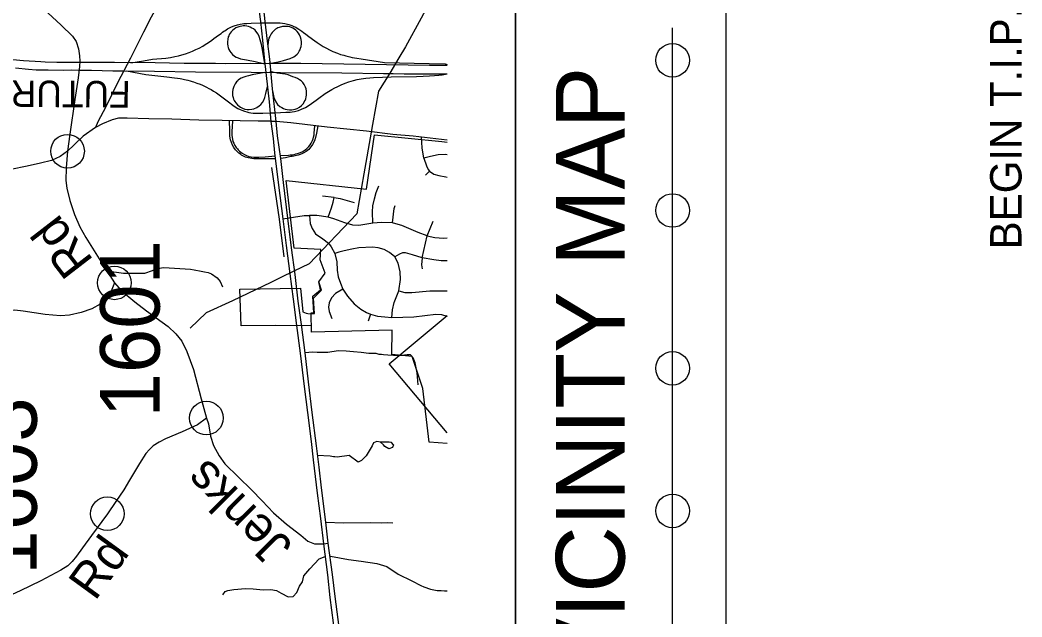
# Model space of a CAD drawing. Extents: x 2026893 to 2039781, y 729195 to 739590.
# Drawn here: x 2027941 to 2028835, y 735115 to 735647 of the extents above; entities that cross this region are included whole.
import ezdxf

# ---------------------------------------------------------------- set-up
doc = ezdxf.new("R2010")
doc.units = 0
doc.layers.add('Old_Level_1', color=7, linetype='Continuous')
doc.layers.add('Old_Level_62', color=7, linetype='Continuous')

msp = doc.modelspace()

# ---------------------------------------------------------------- linework, layer by layer
at = {"layer": 'Old_Level_62'}
for p, q in [((2028523.33, 735033.09), (2028523.33, 735639.94)), ((2027994.64, 735609.1), (2027985.25, 735609.2)), ((2028163.69, 735608.16), (2028159.75, 735608.02)), ((2027986.93, 735602.56), (2027993.99, 735602.17)), ((2027993.99, 735602.17), (2028005.07, 735602.27)), ((2028033.94, 735601.72), (2028061.39, 735601.53)), ((2028159.82, 735600.37), (2028164.29, 735600.62)), ((2028164.41, 735564.14), (2028168.85, 735564.38)), ((2028169.73, 735556.58), (2028165.13, 735556.67)), ((2028306.52, 735512.27), (2028302.91, 735508.83)), ((2028221.56, 735488.9), (2028211.25, 735490)), ((2028304.39, 735454.65), (2028309.91, 735467.73)), ((2028300.15, 735435.14), (2028304.39, 735454.65)), ((2028018.74, 735423.41), (2028025.55, 735412.72)), ((2028185.6, 735423.07), (2028174.06, 735417.51)), ((2028253.8, 735384.7), (2028251.78, 735378.44)), ((2028212.14, 735180.15), (2028216.13, 735180.6))]:
    msp.add_line(p, q, dxfattribs=at)
for points in [[(2027195.27, 734565.89), (2027195.27, 736091.37), (2028383.21, 736091.37), (2028383.21, 734565.89)], [(2028383.21, 734565.89), (2028383.21, 736091.37), (2028570.79, 736091.37), (2028570.79, 734565.89)]]:
    msp.add_lwpolyline(points, close=True, dxfattribs=at)
for points in [[(2027869.52, 735781.98), (2027871.69, 735772.47), (2027872.9, 735768.1), (2027876.18, 735762.11), (2027884.25, 735751.35), (2027895.8, 735736.41), (2027909.27, 735717.87), (2027923.14, 735699.41), (2027933.81, 735686.04), (2027947.48, 735671.05), (2027962.36, 735656.86), (2027977.92, 735642.45), (2027988.16, 735632.6), (2027991.44, 735627.77), (2027993.37, 735621.31), (2027994.44, 735615.03), (2027994.73, 735610.2), (2027994.34, 735605.47), (2027993.23, 735595.53), (2027990.33, 735576.05), (2027985.79, 735545.25), (2027983.71, 735530.05)], [(2028142.72, 735779.53), (2028136.67, 735775.93), (2028131.55, 735772.65), (2028126.43, 735768.5), (2028122.67, 735763.96), (2028114.65, 735752.81), (2028104.7, 735736.23), (2028093.68, 735716.15), (2028077.89, 735686.36), (2028069.34, 735669.59), (2028058.18, 735649.6), (2028051.51, 735636.09), (2028040.01, 735613.13), (2028028.32, 735591.15), (2028017.74, 735569.71), (2028010.69, 735556.29), (2028008.66, 735551.2)], [(2028142.72, 735779.53), (2028144.58, 735762.97), (2028146.18, 735746.9), (2028150.25, 735700.77), (2028152.64, 735669.87), (2028155.92, 735645.7), (2028157.69, 735628.92), (2028159.46, 735610.68), (2028163.44, 735574.12), (2028165.13, 735556.67)], [(2028169.73, 735556.58), (2028166.45, 735585.63), (2028164.15, 735612.19), (2028162.12, 735628.21), (2028159.99, 735645.7), (2028157.95, 735665.71), (2028155.21, 735699.36), (2028153, 735721.58), (2028146.54, 735780.87)], [(2028312.93, 735674.21), (2028299.19, 735648.77), (2028285.22, 735623.05), (2028279.33, 735613.22)], [(2028040.07, 735608.85), (2028051.44, 735610.63), (2028059.43, 735612.03), (2028071.52, 735613.07), (2028075.49, 735613.71), (2028079.46, 735614.41), (2028082.71, 735615.1), (2028085.79, 735615.9), (2028089.07, 735616.94), (2028092.09, 735617.98), (2028095.32, 735619.33), (2028098.23, 735620.62), (2028101.01, 735622.01), (2028104.3, 735623.8), (2028106.51, 735625.08), (2028109.58, 735627.07), (2028112.43, 735629.09), (2028114.34, 735630.45), (2028118.24, 735633.39), (2028120.6, 735635.12), (2028122.08, 735636.23), (2028123.21, 735637.03), (2028123.92, 735637.51), (2028125.15, 735638.3), (2028126.42, 735639.05), (2028127.47, 735639.65), (2028128.68, 735640.24), (2028130.1, 735640.93), (2028132.45, 735641.89), (2028135.32, 735642.76), (2028137.66, 735643.32), (2028139.62, 735643.61), (2028141.06, 735643.8), (2028143.75, 735643.98), (2028147.44, 735644.12), (2028156.03, 735644.62)], [(2028159.75, 735608.02), (2028157.68, 735620.82), (2028156.77, 735625.25), (2028155.66, 735629.28), (2028154.66, 735632.2), (2028153.65, 735634.52), (2028152.64, 735635.93), (2028150.93, 735637.94), (2028149.5, 735639.08), (2028148.11, 735639.88), (2028146.53, 735640.71), (2028145.02, 735641.19), (2028143.71, 735641.5), (2028141.8, 735641.74), (2028140.33, 735641.78), (2028139.06, 735641.66), (2028137.51, 735641.35), (2028135.61, 735640.71), (2028133.9, 735639.96), (2028132.43, 735638.96), (2028131.12, 735637.87), (2028129.69, 735636.38), (2028128.71, 735635.18), (2028128, 735634.03), (2028127.51, 735632.92), (2028127.11, 735632), (2028126.56, 735629.99), (2028126.36, 735627.71), (2028126.36, 735625.74), (2028126.67, 735623.84), (2028126.99, 735622.53), (2028127.69, 735620.82), (2028128.6, 735619.21), (2028129.27, 735618.2), (2028130.84, 735616.31), (2028132.77, 735614.77), (2028134.17, 735613.96), (2028135.88, 735613.19), (2028137.94, 735612.45), (2028143.22, 735611.38), (2028151.13, 735610.08), (2028159.75, 735608.02)], [(2028156.03, 735644.62), (2028165.47, 735644.6), (2028171.31, 735644.6), (2028173.35, 735644.45), (2028175.5, 735644.21), (2028177.46, 735643.95), (2028181.05, 735643.06), (2028183.78, 735642.1), (2028185.51, 735641.37), (2028187.2, 735640.6), (2028188.63, 735639.75), (2028190.16, 735638.79), (2028192.63, 735637.19), (2028194.31, 735635.97), (2028196.34, 735634.42), (2028198.95, 735632.42), (2028200.87, 735630.96), (2028202.2, 735629.92), (2028206.23, 735627.03), (2028208.97, 735625.15), (2028211.62, 735623.47), (2028214.01, 735622.15), (2028217.82, 735620.21), (2028220.47, 735619.04), (2028224.38, 735617.41), (2028227.28, 735616.43), (2028230.12, 735615.55), (2028231.96, 735614.99), (2028235.49, 735614.14), (2028237.48, 735613.71), (2028241.88, 735612.93), (2028245.61, 735612.47), (2028266.41, 735609.1), (2028306.13, 735608.37), (2028320.38, 735607.83), (2028322.2, 735607.51)], [(2028163.69, 735608.16), (2028171.53, 735609.79), (2028176.39, 735610.93), (2028182.29, 735612.74), (2028185.62, 735614.27), (2028186.84, 735615.13), (2028188.4, 735616.45), (2028189.42, 735617.59), (2028190.44, 735619.15), (2028191.1, 735620.41), (2028191.64, 735621.91), (2028192.18, 735623.53), (2028192.48, 735625.7), (2028192.54, 735627.5), (2028192.18, 735629.72), (2028191.64, 735631.64), (2028190.74, 735633.8), (2028189.72, 735635.42), (2028188.48, 735636.93), (2028187.28, 735638.03), (2028186.25, 735638.87), (2028184.61, 735639.88), (2028183.5, 735640.35), (2028182.69, 735640.64), (2028181.96, 735640.83), (2028180.56, 735641.14), (2028179.54, 735641.29), (2028178.47, 735641.37), (2028176.69, 735641.33), (2028175.54, 735641.25), (2028174.55, 735641.08), (2028173.42, 735640.75), (2028172.43, 735640.4), (2028171.31, 735639.93), (2028170.32, 735639.44), (2028169.22, 735638.75), (2028168.34, 735638.01), (2028167.33, 735637.1), (2028166.11, 735635.81), (2028165.37, 735634.74), (2028164.63, 735633.44), (2028164.11, 735632.33), (2028163.37, 735630.85), (2028163, 735629.29), (2028162.6, 735627), (2028162.41, 735624.9)], [(2028279.33, 735613.22), (2028271.25, 735599.74), (2028261.09, 735583.52), (2028255.77, 735553.87), (2028254.57, 735547.13)], [(2027985.25, 735609.2), (2027978.34, 735609.29), (2027974.08, 735609.19), (2027963.64, 735609.55), (2027959.87, 735609.68), (2027944.5, 735610.65), (2027935.04, 735611.58)], [(2027937.32, 735604.3), (2027949.02, 735603.23), (2027955.86, 735602.75), (2027961.27, 735602.56), (2027966.49, 735602.65), (2027979.81, 735602.36), (2027986.93, 735602.56)], [(2028037.81, 735608.99), (2028025.68, 735609.04), (2028002.19, 735609.29), (2027994.66, 735609.2)], [(2028159.75, 735608.02), (2028146.58, 735608.37), (2028124.75, 735608.03), (2028115.79, 735608.14), (2028087.74, 735608.27), (2028048.74, 735609.04), (2028037.81, 735608.99)], [(2028322.2, 735606.39), (2028306.45, 735606.57), (2028191.72, 735608.22), (2028182.43, 735608.13), (2028168.44, 735608.28), (2028163.69, 735608.16)], [(2028005.07, 735602.27), (2028024.21, 735601.59), (2028033.94, 735601.72)], [(2028036.42, 735601.58), (2028053.64, 735598.57), (2028072.21, 735596.26), (2028079.21, 735595.62), (2028081.87, 735595.2), (2028084.18, 735594.78), (2028085.79, 735594.57), (2028088.1, 735594.08), (2028091.04, 735593.31), (2028093, 735592.75), (2028094.89, 735592.26), (2028096.15, 735591.91), (2028099.13, 735590.79), (2028102, 735589.74), (2028104.14, 735588.82), (2028107.56, 735587.21), (2028109.81, 735585.98), (2028111.77, 735584.95), (2028113.87, 735583.68), (2028116.51, 735582.07), (2028118.86, 735580.45), (2028121.35, 735578.64), (2028124.88, 735575.9), (2028127.32, 735573.99), (2028131.13, 735571.17), (2028133.14, 735569.75), (2028135.71, 735568.27), (2028137.66, 735567.22), (2028139.27, 735566.54), (2028141.42, 735565.7), (2028143.7, 735565.04), (2028145.32, 735564.56), (2028147.18, 735564.26), (2028149.22, 735563.96), (2028151.43, 735563.84), (2028153.11, 735563.84), (2028157.79, 735563.9), (2028164.41, 735564.14)], [(2028061.39, 735601.53), (2028097.95, 735600.92), (2028147.46, 735600.58), (2028159.82, 735600.37)], [(2028159.82, 735600.37), (2028148.29, 735598.05), (2028145.07, 735597.38), (2028142.74, 735596.65), (2028140.85, 735596.18), (2028138.65, 735595.15), (2028137.2, 735594.25), (2028135.98, 735593.38), (2028135.51, 735592.95), (2028134.49, 735591.81), (2028133.15, 735590.07), (2028131.9, 735587.63), (2028131.08, 735585.11), (2028130.82, 735583.03), (2028130.79, 735581.11), (2028130.97, 735579.67), (2028131.34, 735578.08), (2028131.86, 735576.53), (2028132.38, 735575.38), (2028132.93, 735574.27), (2028133.74, 735573.19), (2028135.35, 735571.36), (2028136.78, 735570.21), (2028138.1, 735569.23), (2028139.82, 735568.37), (2028141.83, 735567.68), (2028143.95, 735567.28), (2028145.73, 735567.17), (2028148.03, 735567.45), (2028150.03, 735567.97), (2028152.67, 735569.12), (2028154.62, 735570.5), (2028156.17, 735571.76), (2028157.61, 735573.48), (2028158.75, 735575.43), (2028159.79, 735578.02), (2028160.63, 735581.37), (2028162.03, 735587.65)], [(2028163.96, 735600.6), (2028173.72, 735600.29), (2028228.35, 735599.85), (2028265.41, 735599.44), (2028274.03, 735599.3), (2028283.98, 735599.04), (2028322.2, 735599.11)], [(2028166.55, 735583.96), (2028167.84, 735578.02), (2028169.44, 735574.16), (2028171.05, 735571.83), (2028173.13, 735570.07), (2028174.9, 735568.89), (2028176.2, 735568.21), (2028177.9, 735567.53), (2028179.54, 735567.14), (2028181.69, 735566.91), (2028183.9, 735566.97), (2028186.73, 735567.59), (2028188.54, 735568.27), (2028190.53, 735569.35), (2028192.45, 735570.93), (2028194.04, 735572.69), (2028194.89, 735574.05), (2028195.57, 735575.3), (2028196.13, 735576.71), (2028196.59, 735578.47), (2028196.87, 735580.06), (2028196.98, 735581.59), (2028196.87, 735583.51), (2028196.42, 735585.67), (2028195.91, 735587.2), (2028194.66, 735589.51), (2028193.44, 735591.24), (2028191.98, 735592.7), (2028190.49, 735593.84), (2028188.76, 735594.84), (2028186.75, 735595.75), (2028184.63, 735596.38), (2028180.53, 735598.13), (2028177.74, 735598.66), (2028170.76, 735599.53), (2028165.7, 735600.93)], [(2028168.85, 735564.38), (2028178.37, 735564.8), (2028182.14, 735564.92), (2028184.09, 735565.09), (2028186.05, 735565.46), (2028189.65, 735566.32), (2028192.47, 735567.42), (2028196.08, 735569.13), (2028199.38, 735571.15), (2028205.43, 735575.56), (2028207.94, 735577.45), (2028213.55, 735581.5), (2028216.5, 735583.42), (2028219.42, 735585.17), (2028222.1, 735586.65), (2028224.12, 735587.59), (2028227.9, 735589.31), (2028231.2, 735590.6), (2028234.71, 735591.83), (2028238.88, 735593.02), (2028242.07, 735593.85), (2028245.71, 735594.57), (2028249.67, 735595.19), (2028253.23, 735595.55), (2028256.48, 735595.86), (2028264.75, 735596.06), (2028272.43, 735596.47), (2028294.87, 735596.73), (2028300.79, 735596.99), (2028306.62, 735597.25), (2028311.05, 735597.55), (2028314.86, 735597.81), (2028317.9, 735598.07), (2028322.2, 735599.01)], [(2028165.13, 735556.67), (2028164.79, 735556.8), (2028153.87, 735556.9), (2028121.7, 735557.43), (2028100.73, 735557.62), (2028076.68, 735558.54), (2028056.1, 735559.02), (2028036.78, 735559.65), (2028029.24, 735559.55), (2028023.64, 735558.01), (2028014.85, 735554.34), (2028008.66, 735551.2)], [(2028008.66, 735551.2), (2027997.75, 735543.48), (2027989.63, 735535.85), (2027983.71, 735530.05)], [(2028169.03, 735523.39), (2028163.71, 735523.42), (2028159.74, 735523.35), (2028154.27, 735523.26), (2028151.81, 735523.3), (2028149.75, 735523.34), (2028148.02, 735523.49), (2028146.66, 735523.74), (2028144.79, 735524.13), (2028142.5, 735524.9), (2028140.57, 735525.71), (2028138.9, 735526.67), (2028138.03, 735527.29), (2028136.49, 735528.42), (2028134.98, 735529.75), (2028133.44, 735531.41), (2028132, 735533.41), (2028130.8, 735535.57), (2028129.89, 735537.72), (2028129.15, 735540.12), (2028128.6, 735543.51), (2028128.41, 735545.97), (2028128.47, 735548.43), (2028128.1, 735557.23)], [(2028131, 735557.23), (2028130.26, 735547.37), (2028130.32, 735544.11), (2028130.75, 735540.91), (2028131.24, 735538.81), (2028131.98, 735537.28), (2028132.97, 735535.3), (2028134.2, 735533.46), (2028135.24, 735532.16), (2028135.98, 735531.24), (2028137.14, 735530.12), (2028139.46, 735528.28), (2028141.64, 735527), (2028143.43, 735526.19), (2028145.42, 735525.48), (2028147.36, 735525.1), (2028149.82, 735524.82), (2028151.71, 735524.68), (2028154.26, 735524.73), (2028159.97, 735524.92), (2028168.81, 735525.86)], [(2028165.13, 735556.67), (2028167.07, 735541.4), (2028168.4, 735528.52), (2028171.85, 735499.7), (2028175.84, 735469.73), (2028178.85, 735446), (2028181.86, 735420.81), (2028184.87, 735398.19), (2028187.88, 735374.77), (2028191.25, 735350.06), (2028194.79, 735320.36), (2028197.8, 735297.12), (2028200.9, 735271.26), (2028202.84, 735254.84), (2028206.3, 735225.09), (2028209.22, 735202.78), (2028212.14, 735180.15)], [(2028216.13, 735180.6), (2028214.01, 735199.28), (2028210.28, 735230.09), (2028208.07, 735248.55), (2028205.85, 735267.28), (2028202.05, 735297.2), (2028198.77, 735324.43), (2028195.67, 735350.42), (2028192.31, 735375.47), (2028189.56, 735396.33), (2028186.64, 735420.19), (2028183.45, 735444.05), (2028180.35, 735470.52), (2028176.37, 735502.18), (2028173.98, 735523.65), (2028171.06, 735543.7), (2028169.73, 735556.58)], [(2028322.2, 735539.88), (2028291.85, 735543.38), (2028273.84, 735545.1), (2028250.28, 735547.83), (2028215.31, 735551.47), (2028182.74, 735555.25), (2028169.73, 735556.58)], [(2028173.56, 735526.24), (2028180.8, 735526.53), (2028182.43, 735526.69), (2028184.22, 735526.94), (2028185.76, 735527.24), (2028187.47, 735527.61), (2028188.93, 735528.03), (2028190.56, 735528.53), (2028191.56, 735528.99), (2028193.52, 735529.95), (2028195.65, 735531.29), (2028197.07, 735532.55), (2028198.79, 735534.22), (2028200, 735535.73), (2028200.96, 735537.23), (2028201.63, 735538.49), (2028202.24, 735539.71), (2028202.77, 735541.13), (2028203.19, 735542.7), (2028203.55, 735544.59), (2028203.71, 735546.17), (2028204.34, 735552.78)], [(2028206.96, 735552.62), (2028205.68, 735546.01), (2028204.9, 735542.35), (2028203.95, 735539.46), (2028202.19, 735535.93), (2028198.8, 735531.72), (2028196.5, 735529.75), (2028194.47, 735528.5), (2028192.68, 735527.62), (2028191.13, 735527.05), (2028189.41, 735526.57), (2028187.89, 735526.24), (2028185.53, 735525.78), (2028183.99, 735525.49), (2028182.94, 735525.33), (2028181.8, 735525), (2028178.06, 735524.26), (2028173.99, 735523.57)], [(2028178.6, 735503.83), (2028250.37, 735496.16), (2028257.63, 735544.75), (2028317.48, 735538.87), (2028322.2, 735538.18)], [(2028178.6, 735503.83), (2028250.37, 735496.16), (2028257.63, 735544.75), (2028317.48, 735538.87), (2028322.2, 735538.18)], [(2028254.57, 735547.13), (2028247.97, 735509.8), (2028241.82, 735474.39), (2028199.25, 735429.65), (2028185.6, 735423.07)], [(2028301.54, 735523.78), (2028299.99, 735533.06), (2028299.42, 735542.51)], [(2027983.71, 735530.05), (2027977.17, 735525.38), (2027969.34, 735521.9), (2027959.58, 735519.3), (2027947.65, 735516.81), (2027933.02, 735513.67), (2027926.16, 735512.03), (2027920.41, 735509.88), (2027916.69, 735507.23), (2027913.21, 735503.56), (2027906.3, 735495.02), (2027894.52, 735480.25), (2027886.59, 735470.45), (2027881.62, 735464.65)], [(2027983.71, 735530.05), (2027982.36, 735515.16), (2027982.07, 735503.86), (2027983.04, 735497.25), (2027985.84, 735486.05), (2027989.9, 735473.5), (2027994.73, 735462.59), (2028000.14, 735453.27), (2028014.92, 735429.42), (2028018.74, 735423.41)], [(2028322.2, 735526.89), (2028320.62, 735527.04), (2028314.26, 735526.7), (2028307.56, 735525.32), (2028301.54, 735523.78)], [(2028301.54, 735523.78), (2028303.77, 735517.08), (2028305.49, 735513.64), (2028306.52, 735512.27)], [(2028177.03, 735435.98), (2028172.81, 735469.47), (2028165.97, 735515.62)], [(2028306.52, 735512.27), (2028310.48, 735509.69), (2028314.78, 735508.31), (2028321.14, 735507.28), (2028322.2, 735506.99)], [(2028273.16, 735370.64), (2028201.2, 735368.74), (2028201.06, 735385.85), (2028203.53, 735385.85), (2028202.43, 735400.91), (2028209.28, 735406.38), (2028207.91, 735413.5), (2028213.39, 735421.44), (2028209, 735433.21), (2028209.55, 735442.51), (2028186, 735443.61), (2028178.6, 735503.83)], [(2028201.25, 735385.18), (2028204.03, 735385.34), (2028203.07, 735399.09), (2028210.22, 735406.25), (2028207.91, 735413.5), (2028213.39, 735421.44), (2028209, 735433.21), (2028209.55, 735442.51), (2028186, 735443.61), (2028178.6, 735503.83)], [(2028256.12, 735465.88), (2028255.57, 735476.01), (2028256.12, 735481.35), (2028257.41, 735487.61), (2028259.07, 735493.13), (2028261.28, 735499.21)], [(2028216.22, 735471.41), (2028219.17, 735479.51), (2028220.64, 735484.66), (2028221.56, 735488.9)], [(2028221.56, 735488.9), (2028226.91, 735487.79), (2028239.43, 735484.48)], [(2028273.44, 735466.25), (2028274.91, 735479.14), (2028276.02, 735481.53)], [(2028175.84, 735469.73), (2028194.67, 735472.7), (2028199.46, 735472.88)], [(2028199.46, 735472.88), (2028200.19, 735465.7), (2028201.85, 735461.1), (2028204.98, 735456.5), (2028211.43, 735451.89), (2028216.41, 735448.03), (2028218.98, 735444.9), (2028222.12, 735439.01)], [(2028216.22, 735471.41), (2028206.09, 735472.7), (2028199.46, 735472.88)], [(2028256.12, 735465.88), (2028243.45, 735463.86), (2028238.11, 735464.04), (2028231.11, 735466.25), (2028221.38, 735469.93), (2028216.22, 735471.41)], [(2028273.44, 735466.25), (2028263.68, 735466.44), (2028256.12, 735465.88)], [(2028304.39, 735454.65), (2028296.41, 735457.48), (2028281.91, 735463.86), (2028276.57, 735465.33), (2028273.44, 735466.25)], [(2028304.39, 735454.65), (2028311.24, 735453.05), (2028318.97, 735452.54), (2028322.2, 735452.96)], [(2028275.5, 735435.88), (2028270.9, 735439.74), (2028266.11, 735442.5), (2028260.77, 735443.98), (2028255.79, 735444.53), (2028243.63, 735443.98), (2028237.19, 735442.87), (2028230.37, 735441.4), (2028225.58, 735439.93), (2028222.12, 735439.01)], [(2028222.12, 735439.01), (2028223.77, 735431.46), (2028224.14, 735424.1), (2028225.06, 735418.02), (2028227.09, 735412.31), (2028229.3, 735406.97)], [(2028300.15, 735435.14), (2028291.43, 735437.72), (2028285.07, 735439.44), (2028282.4, 735439.35), (2028279.65, 735438.41), (2028275.5, 735435.88)], [(2028279.19, 735405.5), (2028280.66, 735415.63), (2028280.48, 735422.44), (2028278.63, 735430.35), (2028275.5, 735435.88)], [(2028300.15, 735435.14), (2028299.41, 735428.7), (2028300.15, 735425.2)], [(2028322.2, 735432.2), (2028316.92, 735432.2), (2028310.28, 735433.12), (2028300.15, 735435.14)], [(2028018.74, 735423.41), (2028033.73, 735421.25), (2028052.67, 735421.23), (2028059.41, 735423.69), (2028063.04, 735425.23), (2028068.96, 735426.35), (2028074.37, 735426.16), (2028093.51, 735424.82), (2028096.63, 735424.28), (2028102.86, 735423.13), (2028105.97, 735422.5), (2028109.06, 735421.81), (2028112.08, 735420.85), (2028117.05, 735417.27), (2028119.79, 735413.95), (2028121.92, 735409.16)], [(2028174.06, 735417.51), (2028164.97, 735413.13), (2028130.71, 735396.72), (2028107.46, 735385.99), (2028093.14, 735372.39)], [(2028025.55, 735412.72), (2028022.58, 735405.38), (2028018.42, 735398.81), (2028012.91, 735393.69), (2028005.38, 735389.54), (2027995.81, 735386.16), (2027985.57, 735383.99), (2027977.46, 735383.22), (2027963.84, 735384.47), (2027944.08, 735387.59), (2027936.74, 735388.26), (2027922.39, 735387.47), (2027906.25, 735385.92), (2027887.37, 735384.55), (2027870.31, 735383.17)], [(2028025.55, 735412.72), (2028031.44, 735405.92), (2028043.61, 735395.73), (2028054.24, 735387.91), (2028073.56, 735373.67), (2028080.32, 735367.4), (2028085.64, 735360.73), (2028090.08, 735351.51), (2028096.17, 735335.49), (2028102.84, 735309.18), (2028107.57, 735292.19)], [(2028201.21, 735374.49), (2028169.4, 735374.75), (2028138.58, 735374.49), (2028137.54, 735407.14), (2028191.5, 735408.05), (2028193.58, 735386.85), (2028196.57, 735385.68), (2028198, 735385.29), (2028201.25, 735385.18)], [(2028229.3, 735406.97), (2028222.67, 735403.29), (2028219.17, 735399.43), (2028216.96, 735395.01), (2028216.41, 735390.96), (2028216.96, 735387.28), (2028219.54, 735381.02)], [(2028229.3, 735406.97), (2028233.54, 735400.72), (2028239.25, 735393.9), (2028245.33, 735389.12), (2028250.3, 735386.17), (2028253.8, 735384.7)], [(2028272.92, 735381.75), (2028273.48, 735388.56), (2028274.95, 735395.19), (2028279.19, 735405.5)], [(2028279.19, 735405.5), (2028284.68, 735404.03), (2028290.94, 735404.21), (2028306.78, 735405.5), (2028317.65, 735405.69), (2028322.2, 735405.62)], [(2028253.8, 735384.7), (2028260.25, 735383.04), (2028266.7, 735382.31), (2028272.92, 735381.75)], [(2028322.2, 735278.88), (2028270.59, 735340.38), (2028322.2, 735383.69)], [(2028272.92, 735381.75), (2028292.45, 735382.31), (2028312.13, 735384.7), (2028317.28, 735384.51), (2028322.07, 735383.04), (2028322.2, 735382.99)], [(2028273.16, 735370.64), (2028201.2, 735368.74), (2028201.21, 735374.49)], [(2028322.2, 735269.39), (2028306.13, 735270.75), (2028300.75, 735318.55), (2028290.99, 735347.17), (2028272.82, 735348.85), (2028273.16, 735370.64)], [(2028322.2, 735269.39), (2028306.13, 735270.75), (2028300.75, 735318.55), (2028290.99, 735347.17), (2028272.82, 735348.85), (2028273.16, 735370.64)], [(2028215.82, 735350.54), (2028215.56, 735350.53), (2028212.2, 735350.54), (2028206.39, 735350.73), (2028202.22, 735350.9), (2028195.67, 735350.42)], [(2028296.32, 735321.83), (2028295.6, 735332.42), (2028293.79, 735341.33), (2028291.98, 735345.91), (2028289.58, 735348.43), (2028286.68, 735348.55), (2028279.46, 735347.71), (2028269.34, 735348.19), (2028265.48, 735348.55), (2028263.8, 735348.8), (2028261.76, 735348.87), (2028258.86, 735349.64), (2028252.55, 735349.88), (2028245.68, 735350.72), (2028238.69, 735351.2), (2028232.14, 735351.92), (2028225.03, 735352.17), (2028215.82, 735350.54)], [(2028107.57, 735292.19), (2028099.77, 735286.12), (2028085.91, 735279.99), (2028071.08, 735273.78), (2028065.57, 735270.79), (2028060.06, 735267.32), (2028056.87, 735264.23), (2028053.59, 735260.65), (2028047.79, 735251.68), (2028038.95, 735236.78), (2028033.93, 735228.19), (2028026.88, 735217.67), (2028019.24, 735206.86), (2028004.99, 735187.47), (2027996.97, 735176.47), (2027991.85, 735169.13), (2027987.89, 735164.3), (2027983.93, 735160.54), (2027977.65, 735156.58), (2027959.92, 735146.93), (2027941.42, 735138.12), (2027924.08, 735130.13)], [(2028107.57, 735292.19), (2028109.31, 735287.07), (2028111.24, 735276.11), (2028113.95, 735267.81), (2028118.97, 735258.64), (2028124.14, 735251.45), (2028136.26, 735239.45), (2028147.66, 735228.25), (2028157.32, 735218.45), (2028167.52, 735207.57), (2028179.11, 735197.62), (2028191.86, 735187.92), (2028198.06, 735182.54), (2028204, 735180.15), (2028212.14, 735180.15)], [(2028274.3, 735268.23), (2028273.42, 735265.89), (2028270.36, 735264.87), (2028266.86, 735266.77), (2028265.4, 735268.37), (2028262.78, 735270.7), (2028259.72, 735271.14), (2028256.66, 735269.97), (2028255.34, 735267.35), (2028249.95, 735258.61), (2028246.01, 735254.39), (2028242.95, 735252.78), (2028234.79, 735258.76), (2028224.22, 735257.42), (2028222.03, 735257.56), (2028221.01, 735257.71), (2028217.86, 735258.3), (2028206.41, 735258.8)], [(2028274.3, 735268.23), (2028272.63, 735270.37), (2028270.65, 735270.83), (2028262.78, 735270.7)], [(2028214.01, 735199.28), (2028229.76, 735198.88), (2028253.67, 735199.02), (2028263.58, 735198.73), (2028268.97, 735199.02), (2028273.79, 735198.88)], [(2028212.14, 735180.15), (2028215.58, 735152.29), (2028217.79, 735132.19), (2028222.04, 735098.32), (2028223.73, 735086.41), (2028226.56, 735064.94), (2028229.21, 735040.9)], [(2028233.55, 735041.26), (2028230.99, 735064.23), (2028228.59, 735084.11), (2028227.71, 735092.03), (2028222.49, 735133.07), (2028220.18, 735152.64), (2028216.13, 735180.6)], [(2028122.17, 735134.56), (2028124.38, 735137.5), (2028126.58, 735138.42), (2028132.1, 735139.34), (2028142.39, 735140.25), (2028149.19, 735140.07), (2028158.2, 735139.15), (2028165, 735139.34), (2028170.15, 735138.6), (2028174.2, 735136.21), (2028180.45, 735132.72), (2028185.04, 735133.09), (2028188.35, 735136.76), (2028190.56, 735142.28), (2028193.31, 735146.32), (2028194.6, 735151.46), (2028199.75, 735157.89), (2028208.23, 735166.67), (2028213.63, 735168.62)], [(2028218.14, 735168.94), (2028234.31, 735166.16), (2028245.52, 735164.5), (2028259.68, 735162.67), (2028268.41, 735159.73), (2028278.7, 735153.11), (2028290.65, 735147.05), (2028298.74, 735142.83), (2028301.5, 735141.72), (2028307.38, 735139.7), (2028313.45, 735138.42), (2028316.94, 735138.42), (2028319.88, 735138.23), (2028322.09, 735138.05), (2028322.2, 735138.12)]]:
    msp.add_lwpolyline(points, dxfattribs=at)
for centre in [(2028523.33, 735611.12), (2027983.71, 735530.05), (2028523.33, 735477.21), (2028025.55, 735412.72), (2028523.33, 735336.51), (2028107.57, 735292.19), (2028019.24, 735206.86), (2028523.33, 735209.38)]:
    msp.add_circle(centre, 15, dxfattribs=at)

# ---------------------------------------------------------------- texts
at = {"layer": 'Old_Level_1'}
msp.add_text('BEGIN T.I.P. PROJECT B-4697', height=28, rotation=90, dxfattribs=at).set_placement((2028834.56, 735442.57))
at = {"layer": 'Old_Level_62'}
for s, height, rotation, p in [('VICINITY MAP', 61.2502, 90, (2028480.55, 735059.15)), ('FUTURE', 23.622, 179.63197, (2028040.16, 735592.53)), ('Rd', 31.496, 127.64045, (2028007.61, 735432.61)), ('1601', 53.149, 90, (2028065.91, 735292.77)), ('1603', 53.149, 90, (2027956.28, 735152.49)), ('Jenks', 31.496, 135.0859, (2028185.74, 735179.57)), ('Rd', 31.496, 54.02928, (2028008.21, 735128.41))]:
    msp.add_text(s, height=height, rotation=rotation, dxfattribs=at).set_placement(p)

doc.saveas('drawing.dxf')
